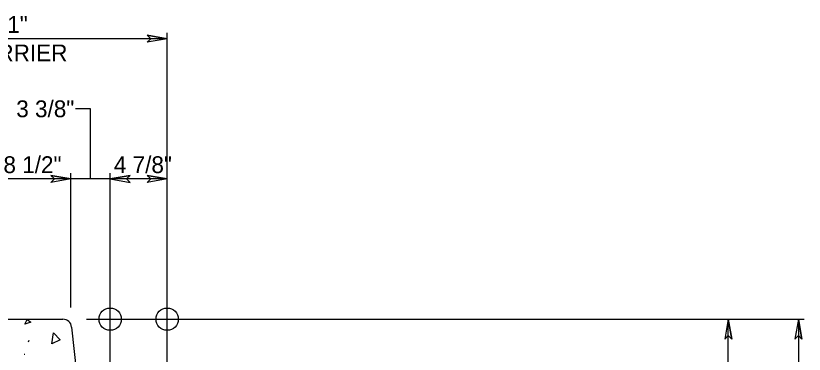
# Model space of a CAD drawing. Extents: x -26.5 to -19.2, y -3.6 to 6.6.
# Drawn here: x -23.277 to -20.466, y 5.371 to 6.577 of the extents above; entities that cross this region are included whole.
import ezdxf

# ---------------------------------------------------------------- set-up
doc = ezdxf.new("R2010")
doc.units = 0
for name, color, linetype in [('ANNO-WOUT', 7, 'Continuous'), ('DETL-DIMS', 7, 'Continuous'), ('DETL-PATT', 7, 'Continuous'), ('Level 10', 7, 'Continuous'), ('Level 12', 7, 'Continuous'), ('SUPR-PARA_P', 7, 'Continuous'), ('SUPR-RFRC', 7, 'Continuous')]:
    doc.layers.add(name, color=color, linetype=linetype)

msp = doc.modelspace()

# ---------------------------------------------------------------- linework, layer by layer
at = {"layer": 'ANNO-WOUT'}
for centre in [(-22.9404, 5.4955), (-22.7373, 5.4955)]:
    msp.add_circle(centre, 0.0397, dxfattribs=at)
at = {"layer": 'DETL-DIMS'}
for p, q in [((-22.737, 6.4955), (-22.8085, 6.508)), ((-22.8085, 6.508), (-22.795, 6.4955)), ((-22.737, 6.4955), (-22.8085, 6.4828)), ((-22.795, 6.4955), (-22.8085, 6.4828)), ((-23.0808, 5.9955), (-23.1523, 5.9828)), ((-23.1388, 5.9955), (-23.1523, 5.9828)), ((-23.0808, 5.9955), (-23.1522, 6.008)), ((-23.1522, 6.008), (-23.1388, 5.9955)), ((-22.9401, 5.9955), (-22.8686, 6.008)), ((-22.9401, 5.9955), (-22.8686, 5.9828)), ((-22.8686, 6.008), (-22.8821, 5.9955)), ((-22.8821, 5.9955), (-22.8686, 5.9828)), ((-22.737, 5.9955), (-22.8085, 6.008)), ((-22.8085, 6.008), (-22.795, 5.9955)), ((-22.737, 5.9955), (-22.8085, 5.9828)), ((-22.795, 5.9955), (-22.8085, 5.9828)), ((-20.737, 5.4955), (-20.7497, 5.424)), ((-20.737, 5.4955), (-20.7245, 5.424)), ((-20.487, 5.4955), (-20.4997, 5.424)), ((-20.487, 5.4955), (-20.4745, 5.424)), ((-20.737, 5.4375), (-20.7497, 5.424)), ((-20.7245, 5.424), (-20.737, 5.4375)), ((-20.487, 5.4375), (-20.4997, 5.424)), ((-20.4745, 5.424), (-20.487, 5.4375))]:
    msp.add_line(p, q, dxfattribs=at)
for points in [[(-22.8085, 6.508), (-22.737, 6.4955), (-22.8085, 6.4828), (-22.795, 6.4955)], [(-23.1522, 6.008), (-23.0808, 5.9955), (-23.1523, 5.9828), (-23.1388, 5.9955)], [(-22.8686, 6.008), (-22.9401, 5.9955), (-22.8686, 5.9828), (-22.8821, 5.9955)], [(-22.8085, 6.008), (-22.737, 5.9955), (-22.8085, 5.9828), (-22.795, 5.9955)], [(-20.7245, 5.424), (-20.737, 5.4955), (-20.7497, 5.424), (-20.737, 5.4375)], [(-20.4745, 5.424), (-20.487, 5.4955), (-20.4997, 5.424), (-20.487, 5.4375)]]:
    msp.add_lwpolyline(points, close=True, dxfattribs=at)
at = {"layer": 'DETL-PATT'}
msp.add_line((-23.2312, 5.4143), (-23.2289, 5.4205), dxfattribs=at)
for points in [[(-23.2451, 5.4777), (-23.2366, 5.4947), (-23.2235, 5.4846), (-23.2451, 5.4777)], [(-23.1478, 5.4073), (-23.1423, 5.4468), (-23.1184, 5.4213), (-23.1478, 5.4073)]]:
    msp.add_lwpolyline(points, dxfattribs=at)
at = {"layer": 'Level 10'}
for p, q in [((-22.737, 6.4955), (-23.7787, 6.4955)), ((-22.737, 3.9121), (-22.737, 6.5163)), ((-23.0104, 6.2455), (-23.0643, 6.2455)), ((-23.0104, 5.9955), (-23.0104, 6.2455)), ((-23.0807, 5.5371), (-23.0807, 6.0163)), ((-22.9401, 4.2462), (-22.9401, 6.0163)), ((-23.0807, 5.9955), (-23.4349, 5.9955)), ((-22.9401, 5.9955), (-23.0807, 5.9955)), ((-22.737, 5.9955), (-22.9401, 5.9955)), ((-23.0243, 5.4955), (-20.4662, 5.4955)), ((-20.737, 4.1636), (-20.737, 5.4955)), ((-20.487, 5.4955), (-20.487, 3.7455))]:
    msp.add_line(p, q, dxfattribs=at)
at = {"layer": 'SUPR-PARA_P'}
for p, q in [((-23.4036, 5.4955), (-23.1089, 5.4955)), ((-23.0778, 5.4676), (-22.954, 4.2941))]:
    msp.add_line(p, q, dxfattribs=at)
msp.add_arc((-23.1089, 5.4643), 0.0312, 6.0207, 90, dxfattribs=at)
at = {"layer": 'SUPR-RFRC'}
msp.add_line((-23.2474, 5.3705), (-23.2451, 5.3705), dxfattribs=at)

# ---------------------------------------------------------------- texts
at = {"layer": 'Level 12'}
for s, p in [('2\'-1"', (-23.394, 6.5163)), ('BARRIER', (-23.4494, 6.4147)), ('3 3/8"', (-23.2752, 6.2155)), ('8 1/2"', (-23.3209, 6.0163)), ('4 7/8"', (-22.9272, 6.0163))]:
    msp.add_text(s, height=0.06001, dxfattribs=at).set_placement(p)

doc.saveas('drawing.dxf')
